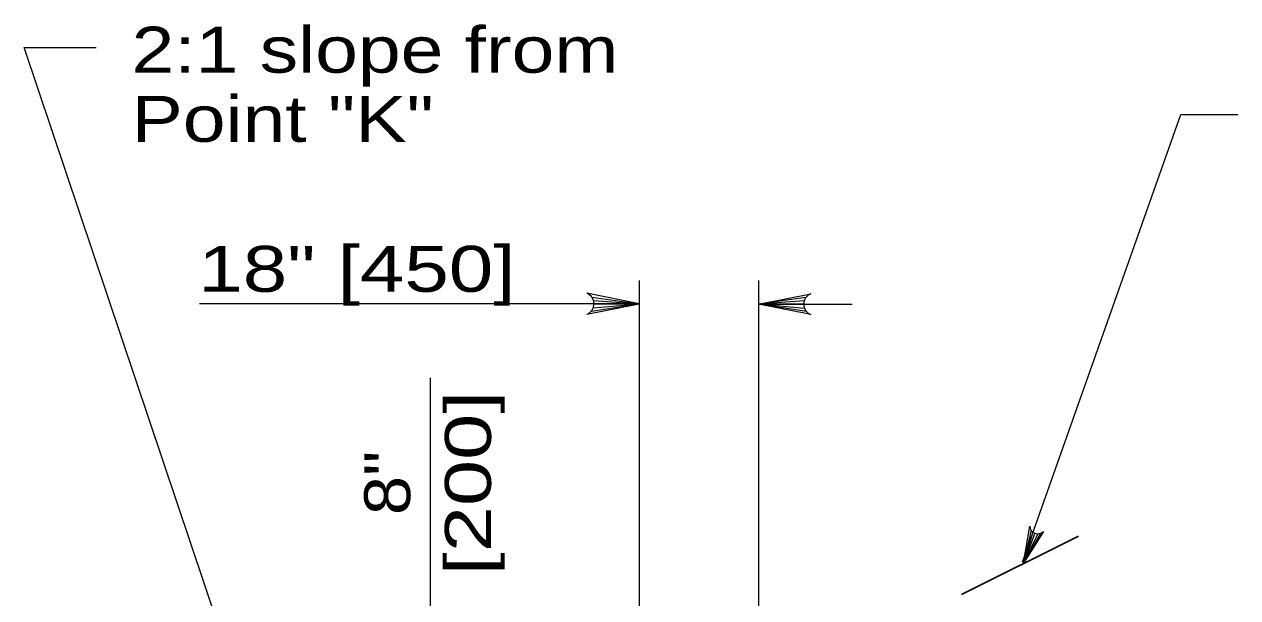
# Model space of a CAD drawing. Extents: x 1083.1 to 1117.1, y 697.4 to 743.4.
# Drawn here: x 1108.584 to 1112.703, y 727.648 to 729.594 of the extents above; entities that cross this region are included whole.
import ezdxf
from ezdxf.enums import TextEntityAlignment as Align

# ---------------------------------------------------------------- set-up
doc = ezdxf.new("R2010")
doc.units = 0
doc.header["$LTSCALE"] = 0.064
doc.layers.add('1', color=7, linetype='Continuous', lineweight=13)

msp = doc.modelspace()

# ---------------------------------------------------------------- linework, layer by layer
at = {"layer": '1'}
for p, q in [((1110.67092, 728.72425), (1110.67108, 727.56458)), ((1111.0765, 728.72442), (1111.07667, 727.56342)), ((1110.51075, 728.668), (1110.671, 728.64558)), ((1110.51617, 728.65692), (1110.671, 728.64558)), ((1111.23683, 728.66667), (1111.07658, 728.64425)), ((1111.23142, 728.65558), (1111.07658, 728.64425)), ((1110.671, 728.64558), (1109.17858, 728.64517)), ((1110.50892, 728.62083), (1110.671, 728.64558)), ((1110.515, 728.63117), (1110.671, 728.64558)), ((1110.51783, 728.64558), (1110.671, 728.64558)), ((1111.07608, 728.64425), (1111.39425, 728.64417)), ((1111.22975, 728.64425), (1111.07658, 728.64425)), ((1111.23258, 728.62992), (1111.07658, 728.64425)), ((1111.23875, 728.6195), (1111.07658, 728.64425)), ((1109.963, 727.46058), (1109.963, 728.39375)), ((1112.00125, 727.877), (1111.97508, 727.76583)), ((1112.00717, 727.87058), (1111.97508, 727.76583)), ((1112.01417, 727.86667), (1111.97508, 727.76583)), ((1112.03275, 727.86625), (1111.97508, 727.76583)), ((1112.02433, 727.86492), (1111.97508, 727.76583))]:
    msp.add_line(p, q, dxfattribs=at)
at = {"layer": '1', "lineweight": 25}
msp.add_line((1111.76475, 727.65842), (1112.16175, 727.85667), dxfattribs=at)
at = {"layer": '1'}
for points in [[(1109.5725, 726.57308), (1108.584, 729.51567), (1108.82758, 729.51567)], [(1111.97217, 727.76892), (1112.50933, 729.28725), (1112.70275, 729.28725)], [(1110.494, 728.61017), (1110.671, 728.64558), (1110.494, 728.681)], [(1111.25358, 728.60883), (1111.07658, 728.64425), (1111.25358, 728.67967)], [(1112.0435, 727.87317), (1111.97508, 727.76583), (1111.99692, 727.89133)]]:
    msp.add_lwpolyline(points, dxfattribs=at)
for centre, start, end in [((1110.47973, 728.64563), 292.08605, 67.91218), ((1111.26789, 728.64432), 112.08782, 247.91395)]:
    msp.add_arc(centre, 0.0382, start, end, dxfattribs=at)
msp.add_ellipse((1112.02384, 727.89176), major_axis=(-0.02577, 0.00794), ratio=0.999895, start_param=0.3146808, end_param=2.6852939, dxfattribs=at)

# ---------------------------------------------------------------- texts
for s, width, p in [('2:1 slope from', 1.25, (1108.94817, 729.42967)), ('Point "K"', 1.25, (1108.94817, 729.195)), ('18" [450]', 1.3, (1109.17483, 728.68608))]:
    msp.add_text(s, height=0.156, dxfattribs=dict(at, width=width)).set_placement(p)
for s, width, p in [('[200]', 1.35, (1110.16792, 728.03742)), ('8"', 1.15, (1109.89392, 728.03742))]:
    msp.add_text(s, height=0.156, rotation=90, dxfattribs=dict(at, width=width)).set_placement(p, align=Align.CENTER)

doc.saveas('drawing.dxf')
